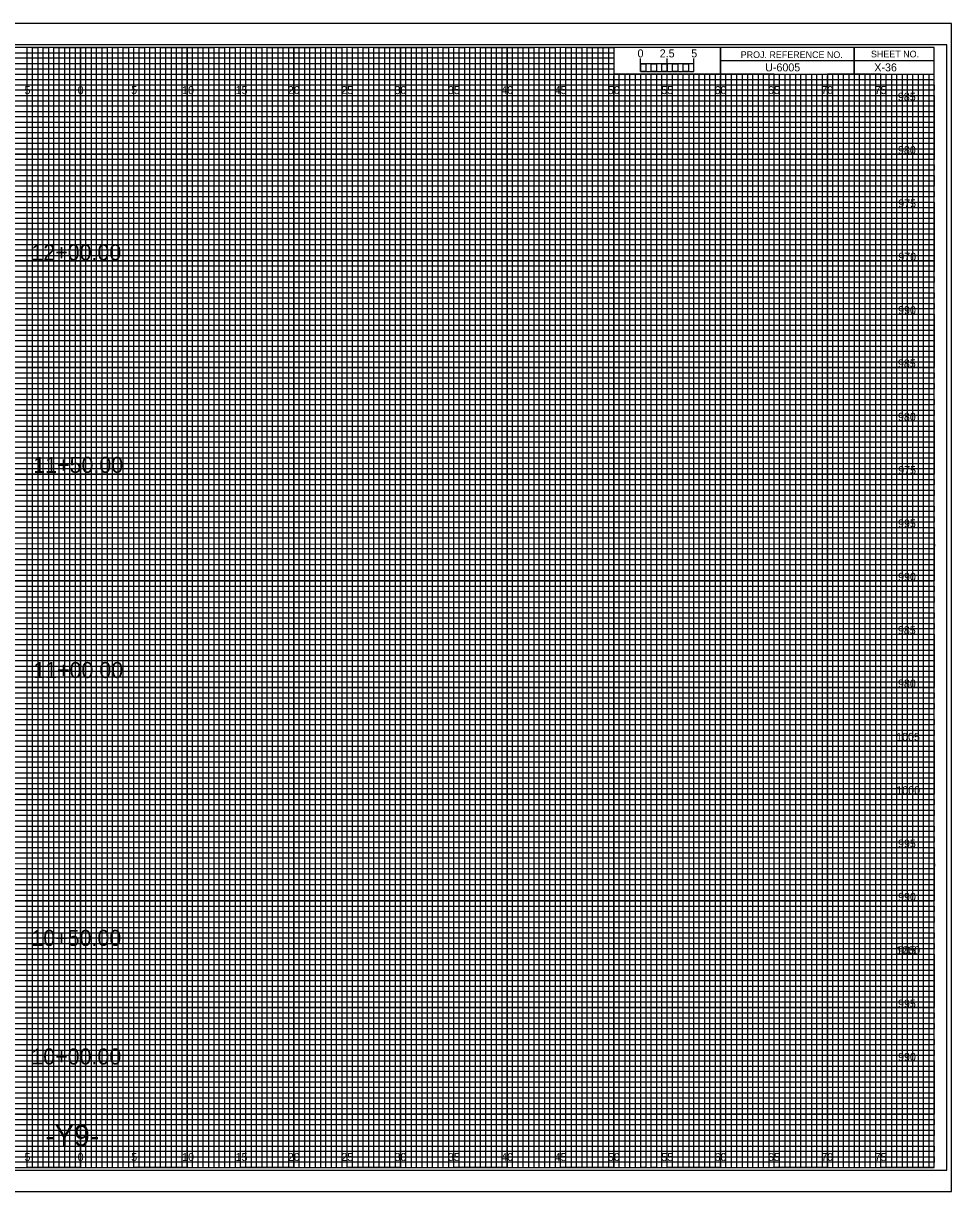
# Model space of a CAD drawing. Extents: x -7 to 162, y -2 to 107.
# Drawn here: x 74.6 to 161.7, y -2.3 to 107.3 of the extents above; entities that cross this region are included whole.
import ezdxf

# ---------------------------------------------------------------- set-up
doc = ezdxf.new("R2010")
doc.units = 0
for name, color, linetype in [('Prop XS Alignment Label', 7, 'Continuous'), ('Prop XS Bar Scale Labels', 7, 'Continuous'), ('Prop XS Elevation Labels', 7, 'Continuous'), ('Prop XS Offset Labels', 7, 'Continuous'), ('Prop XS Project Number', 7, 'Continuous'), ('Prop XS Sheet Number', 7, 'Continuous'), ('Prop XS Station Labels', 7, 'Continuous'), ('Sheet Cross Section CELL', 7, 'Continuous'), ('Sheet Cross Section Grid Major CELL', 7, 'Continuous'), ('Sheet Cross Section Grid Middle CELL', 7, 'Continuous'), ('Sheet Cross Section Grid Minor 1 CELL', 7, 'Continuous'), ('Sheet Cross Section Grid Minor 2 CELL', 7, 'Continuous'), ('Sheet Cross Section Scale CELL', 7, 'Continuous'), ('Sheet Cutting Line CELL', 7, 'Continuous'), ('Sheet DOT Grid CELL', 7, 'Continuous'), ('Sheet Plot Border Inside CELL', 7, 'Continuous'), ('Sheet Plot Border Outside CELL', 7, 'Continuous')]:
    doc.layers.add(name, color=color, linetype=linetype)

msp = doc.modelspace()

# ---------------------------------------------------------------- linework, layer by layer
at = {"layer": 'Sheet Cross Section CELL'}
for p, q in [((152.5, 105), (152.5, 102.5)), ((152.5, 102.5), (152.5, 105)), ((160, 103.75), (140, 103.75)), ((140, 103.75), (140, 102.5)), ((140, 102.5), (160, 102.5))]:
    msp.add_line(p, q, dxfattribs=at)
for points in [[(160, 105), (0, 105), (0, 0), (160, 0)], [(140, 105), (130, 105), (130, 102.52), (140, 102.52)], [(160, 105), (140, 105), (140, 102.5), (160, 102.5)]]:
    msp.add_lwpolyline(points, close=True, dxfattribs=at)
at = {"layer": 'Sheet Cross Section Grid Major CELL'}
for p, q in [((75, 105), (70, 105)), ((75, 0), (75, 105)), ((85, 105), (80, 105)), ((80, 105), (80, 0)), ((85, 0), (85, 105)), ((95, 105), (90, 105)), ((90, 105), (90, 0)), ((95, 0), (95, 105)), ((105, 105), (100, 105)), ((100, 105), (100, 0)), ((105, 0), (105, 105)), ((115, 105), (110, 105)), ((110, 105), (110, 0)), ((115, 0), (115, 105)), ((125, 105), (120, 105)), ((120, 105), (120, 0)), ((125, 0), (125, 105)), ((130, 105), (130, 0)), ((135, 0), (135, 102.5)), ((145, 102.5), (140, 102.5)), ((140, 102.5), (140, 0)), ((145, 0), (145, 102.5)), ((155, 102.5), (150, 102.5)), ((150, 102.5), (150, 0)), ((155, 0), (155, 102.5)), ((80, 0), (75, 0)), ((90, 0), (85, 0)), ((100, 0), (95, 0)), ((110, 0), (105, 0)), ((120, 0), (115, 0)), ((130, 0), (125, 0)), ((140, 0), (135, 0)), ((150, 0), (145, 0)), ((160, 0), (155, 0)), ((160, 0), (160, 0))]:
    msp.add_line(p, q, dxfattribs=at)
for points in [[(0, 100), (160, 100), (160, 95), (0, 95)], [(0, 90), (160, 90), (160, 85), (0, 85)], [(0, 80), (160, 80), (160, 75), (0, 75)], [(0, 70), (160, 70), (160, 65), (0, 65)], [(0, 60), (160, 60), (160, 55), (0, 55)], [(0, 50), (160, 50), (160, 45), (0, 45)], [(0, 40), (160, 40), (160, 35), (0, 35)], [(0, 30), (160, 30), (160, 25), (0, 25)], [(0, 20), (160, 20), (160, 15), (0, 15)], [(0, 10), (160, 10), (160, 5), (0, 5)]]:
    msp.add_lwpolyline(points, dxfattribs=at)
at = {"layer": 'Sheet Cross Section Grid Middle CELL'}
for points in [[(72.5, 0), (77.5, 0), (77.5, 105), (82.5, 105), (82.5, 0), (87.5, 0), (87.5, 105), (92.5, 105), (92.5, 0), (97.5, 0), (97.5, 105), (102.5, 105), (102.5, 0), (107.5, 0), (107.5, 105), (112.5, 105), (112.5, 0), (117.5, 0), (117.5, 105), (122.5, 105), (122.5, 0), (127.5, 0), (127.5, 105), (129.97, 105), (130, 105), (130, 102.5), (132.5, 102.5), (132.5, 0), (137.5, 0), (137.5, 102.5), (142.5, 102.5), (142.5, 0), (147.5, 0), (147.5, 102.5), (152.5, 102.5), (152.5, 0), (157.5, 0), (157.5, 102.5)], [(0, 102.5), (137.5, 102.5)], [(0, 92.5), (160, 92.5), (160, 97.5), (0, 97.5)], [(0, 82.5), (160, 82.5), (160, 87.5), (0, 87.5)], [(0, 72.5), (160, 72.5), (160, 77.5), (0, 77.5)], [(0, 62.5), (160, 62.5), (160, 67.5), (0, 67.5)], [(0, 52.5), (160, 52.5), (160, 57.5), (0, 57.5)], [(0, 42.5), (160, 42.5), (160, 47.5), (0, 47.5)], [(0, 32.5), (160, 32.5), (160, 37.5), (0, 37.5)], [(0, 22.5), (160, 22.5), (160, 27.5), (0, 27.5)], [(0, 12.5), (160, 12.5), (160, 17.5), (0, 17.5)], [(0, 2.5), (160, 2.5), (160, 7.5), (0, 7.5)]]:
    msp.add_lwpolyline(points, dxfattribs=at)
at = {"layer": 'Sheet Cross Section Grid Minor 1 CELL'}
for p, q in [((0, 104.5), (130, 104.5)), ((130, 104.5), (130, 103.99)), ((130, 103.99), (0, 103.99)), ((0, 103.5), (130, 103.5)), ((130, 102.95), (0, 102.95)), ((130, 103.5), (130, 102.95)), ((0, 102), (160, 102))]:
    msp.add_line(p, q, dxfattribs=at)
for points in [[(0, 101.5), (135, 101.5), (160, 101.5), (160, 101), (0, 101)], [(0, 100.5), (160, 100.5), (160, 99.5), (0, 99.5)], [(0, 99), (160, 99), (160, 98.5), (0, 98.49)], [(0, 98), (160, 98), (160, 97), (0, 97)], [(0, 96.5), (160, 96.5), (160, 96), (0, 96)], [(0, 95.5), (160, 95.5), (160, 94.5), (0, 94.5)], [(0, 94), (160, 94), (160, 93.5), (0, 93.5)], [(0, 93), (160, 93), (160, 92), (0, 92)], [(0, 91.5), (160, 91.5), (160, 91), (0, 91)], [(0, 90.5), (160, 90.5), (160, 89.5), (0, 89.5)], [(0, 89), (160, 89), (160, 88.5), (0, 88.5)], [(0, 88), (160, 88), (160, 86.98), (160, 86.5), (160, 86), (0, 86)], [(0, 87), (160, 87), (160, 86.5), (0, 86.5)], [(0, 85.5), (160, 85.5), (160, 84.5), (0, 84.52)], [(0, 84.52), (160, 84.5), (160, 84), (0, 84)], [(0, 83.5), (160, 83.5), (160, 83), (0, 83)], [(0, 82), (160, 82), (160, 81.5), (0, 81.5)], [(0, 81), (160, 81), (160, 80.5), (0, 80.5)], [(-0.04, 79.45), (160, 79.45), (160, 78.94), (-0.04, 78.94)], [(0, 78.5), (160, 78.5), (160, 78), (0, 78)], [(0, 77), (160, 77), (160, 76.5), (0, 76.5)], [(0, 76), (160, 76), (160, 75.5), (0, 75.5)], [(0, 74.5), (160, 74.5), (160, 74), (0, 74)], [(0, 73.5), (160, 73.5), (160, 73), (0, 73)], [(0, 72), (160, 72), (160, 71.5), (0, 71.5)], [(0, 71), (160, 71), (160, 70.5), (0, 70.5)], [(0, 69.5), (160, 69.5), (160, 68.99), (0, 69)], [(0, 68.5), (160, 68.5), (160, 68), (0, 68)], [(0, 67), (160, 67), (160, 66.5), (0, 66.5)], [(0, 66), (160, 66), (160, 65.5), (0, 65.5)], [(0, 64.5), (160, 64.5), (160, 64), (0, 64)], [(0, 63.5), (160, 63.5), (160, 63), (0, 63)], [(0, 62), (160, 62), (160, 61.5), (0, 61.5)], [(0, 61), (160, 61), (160, 60.5), (0, 60.5)], [(0, 59.5), (160, 59.5), (160, 59), (0, 59)], [(0, 58.5), (160.03, 58.45), (160, 58), (0, 58)], [(0, 57), (160, 57), (160, 56.5), (0, 56.5)], [(0, 56), (160, 56), (160, 55.5), (0, 55.5)], [(0, 54.5), (160, 54.5), (160, 54), (0, 54)], [(0, 53.5), (160, 53.5), (160, 53), (0, 53)], [(0, 52), (160, 52), (160, 51.5), (0, 51.5)], [(0, 51), (160, 51), (160, 50.5), (0, 50.5)], [(0, 49.5), (160, 49.5), (160, 49), (0, 49)], [(0, 48.5), (160, 48.5), (160, 48), (0, 48)], [(0, 47), (160, 47), (160, 46.5), (0, 46.5)], [(0, 46), (160, 46), (160, 45.5), (0, 45.5)], [(0, 44.5), (160, 44.5), (160, 44), (0, 44)], [(0, 43.5), (160, 43.5), (160, 43), (0, 43)], [(0, 42), (160, 42), (160, 41.5), (0, 41.5)], [(0, 41), (160, 41), (160, 40.5), (0, 40.5)], [(0, 39.5), (160, 39.5), (160, 38.99), (0, 39)], [(0, 38.5), (160, 38.5), (160, 38), (0, 38)], [(0, 37), (160, 37), (160, 36.5), (0, 36.5)], [(0, 36), (160, 36), (160, 35.5), (0, 35.5)], [(0, 34.5), (160, 34.5), (160, 34), (0, 34)], [(0, 33.5), (160, 33.5), (160, 33), (0, 33)], [(0, 32), (160, 32), (160, 31.5), (0, 31.5)], [(0, 31), (160, 31), (160, 30.5), (0, 30.5)], [(0, 29.5), (160, 29.5), (160, 29), (0, 29)], [(0, 28.5), (160.03, 28.46), (160, 28), (0, 28)], [(0, 27), (160, 27), (160, 26.5), (0, 26.5)], [(0, 26), (160, 26), (160, 25.5), (0, 25.5)], [(0, 24.5), (160, 24.5), (160, 24), (0, 24)], [(0, 23.5), (160, 23.5), (160, 23), (0, 23)], [(0, 22), (160, 22), (160, 21.5), (0, 21.5)], [(0, 21), (160, 21), (160, 20.5), (0, 20.5)], [(0, 19.5), (160, 19.5), (160, 19), (0, 19)], [(0, 18.5), (160, 18.5), (160, 18), (0, 18)], [(0, 17), (160, 17), (160, 16.5), (0, 16.5)], [(0, 16), (160, 16), (160, 15.5), (0, 15.5)], [(0, 14.5), (160, 14.5), (160, 14), (0, 14)], [(0, 13.5), (160, 13.5), (160, 13), (0, 13)], [(0, 12), (160, 12), (160, 11.5), (0, 11.5)], [(0, 11), (160, 11), (160, 10.5), (0, 10.5)], [(0, 9.5), (160, 9.5), (160, 9), (0, 9)], [(0, 8.5), (160, 8.5), (160, 8), (0, 8)], [(0, 7), (160, 7), (160, 6.5), (0, 6.5)], [(0, 6), (160, 6), (160, 5.5), (0, 5.5)], [(0, 4.5), (160, 4.5), (160, 4), (0, 4)], [(0, 3.5), (160, 3.5), (160, 3), (0, 3)], [(0, 2), (160, 2), (160, 1.5), (0, 1.5)], [(0, 1), (160, 1), (160, 0.5), (0, 0.5)]]:
    msp.add_lwpolyline(points, dxfattribs=at)
at = {"layer": 'Sheet Cross Section Grid Minor 2 CELL'}
for p, q in [((133.5, 102.5), (133, 102.5)), ((133, 102.5), (133, 0)), ((133.5, 0), (133.5, 102.5)), ((134.5, 102.5), (134, 102.5)), ((134, 102.5), (134, 0)), ((134.5, 0), (134.5, 102.5)), ((133, 0), (132.5, 0)), ((134, 0), (133.5, 0))]:
    msp.add_line(p, q, dxfattribs=at)
for points in [[(75, 0), (75.5, 0), (75.5, 105), (76, 105), (76, 0)], [(76, 0), (76.5, 0), (76.5, 105), (77, 105), (77, 0)], [(77.5, 0), (78, 0), (78, 105), (78.5, 105), (78.5, 0)], [(78.5, 0), (79, 0), (79, 105), (79.5, 105), (79.5, 0)], [(80, 0), (80.5, 0), (80.5, 105), (81, 105), (81, 0)], [(81, 0), (81.5, 0), (81.5, 105), (82, 105), (82, 0)], [(82.5, 0), (83, 0), (83, 105), (83.5, 105), (83.5, 0)], [(83.5, 0), (84, 0), (84, 105), (84.5, 105), (84.5, 0)], [(85, 0), (85.5, 0), (85.5, 105), (86, 105), (86, 0)], [(86, 0), (86.5, 0), (86.5, 105), (87, 105), (87, 0)], [(87.5, 0), (88, 0), (88, 105), (88.5, 105), (88.5, 0)], [(88.5, 0), (89, 0), (89, 105), (89.5, 105), (89.5, 0)], [(90, 0), (90.5, 0), (90.5, 105), (91, 105), (91, 0)], [(91, 0), (91.5, 0), (91.5, 105), (92, 105), (92, 0)], [(92.5, 0), (93, 0), (93, 105), (93.5, 105), (93.5, 0)], [(93.5, 0), (94, 0), (94, 105), (94.5, 105), (94.5, 0)], [(95, 0), (95.5, 0), (95.5, 105), (96, 105), (96, 0)], [(96, 0), (96.5, 0), (96.5, 105), (97, 105), (97, 0)], [(97.5, 0), (98, 0), (98, 105), (98.5, 105), (98.5, 0)], [(98.5, 0), (99, 0), (99, 105), (99.5, 105), (99.5, 0)], [(100, 0), (100.5, 0), (100.5, 105), (101, 105), (101, 0)], [(101, 0), (101.5, 0), (101.5, 105), (102, 105), (102, 0)], [(102.5, 0), (103, 0), (103, 105), (103.5, 105), (103.5, 0)], [(103.5, 0), (104, 0), (104, 105), (104.5, 105), (104.5, 0)], [(105, 0), (105.5, 0), (105.5, 105), (106, 105), (106, 0)], [(106, 0), (106.5, 0), (106.5, 105), (107, 105), (107, 0)], [(107.5, 0), (108, 0), (108, 105), (108.5, 105), (108.5, 0)], [(108.5, 0), (109, 0), (109, 105), (109.5, 105), (109.5, 0)], [(110, 0), (110.5, 0), (110.5, 105), (111, 105), (111, 0)], [(111, 0), (111.5, 0), (111.5, 105), (112, 105), (112, 0)], [(112.5, 0), (113, 0), (113, 105), (113.5, 105), (113.5, 0)], [(113.5, 0), (114, 0), (114, 105), (114.5, 105), (114.5, 0)], [(115, 0), (115.5, 0), (115.5, 105), (116, 105), (116, 0)], [(116, 0), (116.5, 0), (116.5, 105), (117, 105), (117, 0)], [(117.5, 0), (118, 0), (118, 105), (118.5, 105), (118.5, 0)], [(118.5, 0), (119, 0), (119, 105), (119.5, 105), (119.5, 0)], [(120, 0), (120.5, 0), (120.5, 105), (121, 105), (121, 0)], [(121, 0), (121.5, 0), (121.5, 105), (122, 105), (122, 0)], [(122.5, 0), (123, 0), (123, 105), (123.5, 105), (123.5, 0)], [(123.5, 0), (124, 0), (124, 105), (124.5, 105), (124.5, 0)], [(125, 0), (125.5, 0), (125.5, 105), (126, 105), (126, 0)], [(126, 0), (126.5, 0), (126.5, 105), (127, 105), (127, 0)], [(127.5, 0), (128, 0), (128, 105), (128.5, 105), (128.5, 0)], [(128.5, 0), (129, 0), (129, 105), (129.5, 105), (129.5, 0)], [(130, 0), (130.5, 0), (130.5, 102.5), (131.01, 102.5), (131.01, 0)], [(131, 0), (131.5, 0), (131.5, 102.5), (132, 102.5), (132, 0)], [(135, 0), (135.49, 0), (135.49, 102.5), (136, 102.5), (136, 0)], [(136, 0), (136.5, 0), (136.5, 102.5), (137.03, 102.5), (137.03, 0)], [(137.5, 0), (138, 0), (138, 102.5), (138.5, 102.5), (138.5, 0)], [(138.5, 0), (139, 0), (139, 102.5), (139.5, 102.5), (139.5, 0)], [(140, 0), (140.5, 0), (140.5, 102.5), (141, 102.5), (141, 0)], [(141, 0), (141.5, 0), (141.5, 102.5), (142, 102.5), (142, 0)], [(142.5, 0), (143, 0), (143, 102.5), (143.5, 102.5), (143.5, 0)], [(143.5, 0), (144, 0), (144, 102.5), (144.5, 102.5), (144.5, 0)], [(145, 0), (145.5, 0), (145.5, 102.5), (146, 102.5), (146, 0)], [(146, 0), (146.5, 0), (146.5, 102.5), (147, 102.5), (147, 0)], [(147.5, 0), (148, 0), (148, 102.5), (148.5, 102.5), (148.5, 0)], [(148.5, 0), (149, 0), (149, 102.5), (149.5, 102.5), (149.5, 0)], [(150, 0), (150.5, 0), (150.5, 102.5), (151, 102.5), (151, 0)], [(151, 0), (151.5, 0), (151.5, 102.5), (152, 102.5), (152, 0)], [(152.5, 0), (153, 0), (153, 102.5), (153.5, 102.5), (153.5, 0)], [(153.5, 0), (154, 0), (154, 102.5), (154.5, 102.5), (154.5, 0)], [(155, 0), (155.5, 0), (155.5, 102.5), (156, 102.5), (156, 0)], [(156, 0), (156.5, 0), (156.5, 102.5), (157, 102.5), (157, 0)], [(157.5, 0), (158, 0), (158, 102.5), (158.5, 102.5), (158.5, 0)], [(158.5, 0), (159, 0), (159, 102.5), (159.5, 102.5), (159.5, 0)]]:
    msp.add_lwpolyline(points, dxfattribs=at)
at = {"layer": 'Sheet Cross Section Scale CELL'}
for p, q in [((132.5, 102.75), (132.5, 103.95)), ((132.5, 103.45), (132.5, 103.95)), ((135, 102.75), (135, 103.95)), ((137.5, 102.75), (137.5, 103.95)), ((137.5, 103.45), (137.5, 103.95))]:
    msp.add_line(p, q, dxfattribs=at)
for points in [[(137.5, 103.45), (132.5, 103.45), (132.5, 102.75), (137.5, 102.75)], [(132.5, 103.45), (133, 103.45), (133, 102.75), (132.5, 102.75)], [(133.5, 103.45), (134, 103.45), (134, 102.75), (133.5, 102.75)], [(134.5, 103.45), (135, 103.45), (135, 102.75), (134.5, 102.75)], [(135.5, 103.45), (136, 103.45), (136, 102.75), (135.5, 102.75)], [(136.5, 103.45), (137, 103.45), (137, 102.75), (136.5, 102.75)]]:
    msp.add_lwpolyline(points, close=True, dxfattribs=at)
at = {"layer": 'Sheet Cutting Line CELL'}
for p, q in [((161.65, 107.25), (-6.7, 107.25)), ((-6.7, -2.25), (161.65, -2.25))]:
    msp.add_line(p, q, dxfattribs=at)
at = {"layer": 'Sheet DOT Grid CELL'}
for p, q in [((75, 0), (75, 105)), ((80, 0), (80, 105)), ((85, 0), (85, 105)), ((90, 0), (90, 105)), ((95, 0), (95, 105)), ((100, 0), (100, 105)), ((105, 0), (105, 105)), ((110, 0), (110, 105)), ((115, 0), (115, 105)), ((120, 0), (120, 105)), ((125, 0), (125, 105)), ((130, 0), (130, 102.34)), ((135, 0), (135, 102.34)), ((140, 0), (140, 102.34)), ((145, 0), (145, 102.34)), ((150, 0), (150, 102.34)), ((155, 0), (155, 102.34)), ((0, 100), (160, 100)), ((0, 95), (160, 95)), ((0, 90), (160, 90)), ((0, 85), (160, 85)), ((0, 80), (160, 80)), ((0, 75), (160, 75)), ((0, 70), (160, 70)), ((0, 65), (160, 65)), ((0, 60), (160, 60)), ((0, 55), (160, 55)), ((0, 50), (160, 50)), ((0, 45), (160, 45)), ((0, 40), (160, 40)), ((0, 35), (160, 35)), ((0, 30), (160, 30)), ((0, 25), (160, 25)), ((0, 20), (160, 20)), ((0, 15), (160, 15)), ((0, 10), (160, 10)), ((0, 5), (160, 5))]:
    msp.add_line(p, q, dxfattribs=at)
at = {"layer": 'Sheet Plot Border Inside CELL'}
msp.add_lwpolyline([(-5.4, -0.25), (161.2, -0.25), (161.2, 105.25), (-5.4, 105.25)], close=True, dxfattribs=at)
at = {"layer": 'Sheet Plot Border Outside CELL'}
msp.add_lwpolyline([(-6.7, -2.25), (161.65, -2.25), (161.65, 107.25), (-6.7, 107.25)], close=True, dxfattribs=at)

# ---------------------------------------------------------------- texts
at = {"layer": 'Prop XS Alignment Label'}
msp.add_text('-Y9-', height=2, dxfattribs=at).set_placement((76.7, 2))
at = {"layer": 'Prop XS Bar Scale Labels'}
for s, p in [('2.5', (134.29, 104.06)), ('5', (137.24, 104.06))]:
    msp.add_text(s, height=0.75, dxfattribs=at).set_placement(p)
at = {"layer": 'Prop XS Elevation Labels'}
for s, p in [('985', (156.61, 100)), ('980', (156.62, 95)), ('975', (156.64, 90)), ('970', (156.65, 85)), ('990', (156.63, 80)), ('985', (156.61, 75)), ('980', (156.62, 70)), ('975', (156.64, 65)), ('995', (156.62, 60)), ('990', (156.63, 55)), ('985', (156.61, 50)), ('980', (156.62, 45)), ('1005', (156.45, 40)), ('1000', (156.46, 35)), ('995', (156.62, 30)), ('990', (156.63, 25)), ('1000', (156.46, 20)), ('985', (156.61, 20)), ('995', (156.62, 15)), ('990', (156.63, 10))]:
    msp.add_text(s, height=0.75, dxfattribs=at).set_placement(p)
at = {"layer": 'Prop XS Offset Labels'}
for s, p in [('5', (74.74, 100.62)), ('0', (79.73, 100.62)), ('0', (79.73, 100.62)), ('5', (84.74, 100.62)), ('10', (89.52, 100.62)), ('15', (94.53, 100.62)), ('20', (99.43, 100.62)), ('25', (104.44, 100.62)), ('30', (109.43, 100.62)), ('35', (114.44, 100.62)), ('40', (119.43, 100.62)), ('45', (124.44, 100.62)), ('50', (129.43, 100.62)), ('55', (134.44, 100.62)), ('60', (139.43, 100.62)), ('65', (144.44, 100.62)), ('70', (149.43, 100.62)), ('75', (154.44, 100.62)), ('5', (74.74, 0.62)), ('0', (79.73, 0.62)), ('0', (79.73, 0.62)), ('5', (84.74, 0.62)), ('10', (89.52, 0.62)), ('15', (94.53, 0.62)), ('20', (99.43, 0.62)), ('25', (104.44, 0.62)), ('30', (109.43, 0.62)), ('35', (114.44, 0.62)), ('40', (119.43, 0.62)), ('45', (124.44, 0.62)), ('50', (129.43, 0.62)), ('55', (134.44, 0.62)), ('60', (139.43, 0.62)), ('65', (144.44, 0.62)), ('70', (149.43, 0.62)), ('75', (154.44, 0.62))]:
    msp.add_text(s, height=0.75, dxfattribs=at).set_placement(p)
at = {"layer": 'Prop XS Project Number'}
msp.add_text('U-6005', height=0.75, dxfattribs=at).set_placement((144.17, 102.75))
at = {"layer": 'Prop XS Sheet Number'}
msp.add_text('X-36', height=0.75, dxfattribs=at).set_placement((154.4, 102.75))
at = {"layer": 'Prop XS Station Labels'}
for s, p in [('12+00.00', (75.39, 85.04)), ('11+50.00', (75.57, 65.12)), ('11+00.00', (75.57, 45.89)), ('10+50.00', (75.39, 20.78)), ('10+00.00', (75.39, 9.67))]:
    msp.add_text(s, height=1.5, dxfattribs=at).set_placement(p)
at = {"layer": 'Sheet Cross Section CELL'}
for s, p in [('PROJ. REFERENCE NO.', (141.88, 104)), ('SHEET NO.', (154.09, 104.06))]:
    msp.add_text(s, height=0.625, dxfattribs=at).set_placement(p)
at = {"layer": 'Sheet Cross Section Scale CELL'}
msp.add_text('0', height=0.75, dxfattribs=at).set_placement((132.21, 104.06))

doc.saveas('drawing.dxf')
